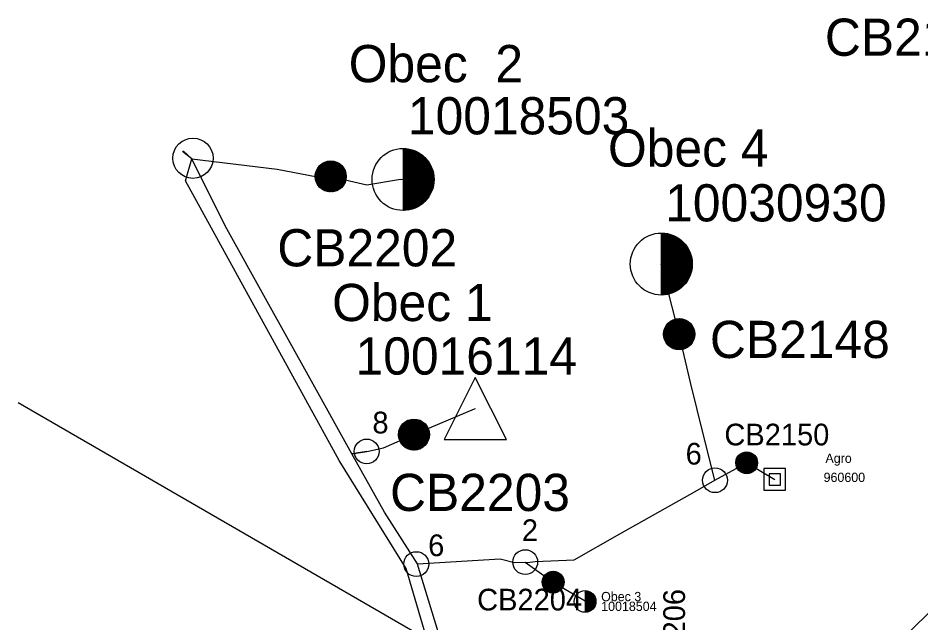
# Model space of a CAD drawing. Extents: x -763722 to -759486, y -1156407 to -1150938.
# Drawn here: x -763541 to -762085, y -1152498 to -1151523 of the extents above; entities that cross this region are included whole.
import ezdxf

# ---------------------------------------------------------------- set-up
doc = ezdxf.new("R2010")
doc.units = 0
for name, color, linetype in [('Default', 7, 'Continuous'), ('Vrstva 1', 7, 'Continuous'), ('Vrstva 18', 7, 'Continuous'), ('Vrstva 2', 7, 'Continuous'), ('Vrstva 3', 7, 'Continuous'), ('Vrstva 44', 7, 'Continuous'), ('Vrstva 5', 7, 'Continuous')]:
    doc.layers.add(name, color=color, linetype=linetype)

# ---------------------------------------------------------------- blocks, each defined once
blk = doc.blocks.new('PS140')
at = {"layer": 'Default'}
for p, q in [((-17.5, 0), (0, 17.5)), ((-17.4, -1.4), (1.4, 17.4)), ((-17.4, 1.5), (-1.5, 17.4)), ((-17.3, -2.6), (2.6, 17.3)), ((-17.2, 3.1), (-3.1, 17.2)), ((-17.1, -3.8), (3.8, 17.1)), ((-16.8, -4.9), (4.9, 16.8)), ((-16.8, 5), (-5, 16.8)), ((-16.4, -6), (6, 16.4)), ((-16, -7), (7, 16)), ((-15.9, 7.2), (-7.2, 15.9)), ((-15.6, -8), (8, 15.6)), ((-15.1, -8.9), (8.9, 15.1)), ((-14.5, -9.8), (9.8, 14.5)), ((-13.9, -10.6), (10.6, 13.9)), ((-13.8, 10.8), (-10.8, 13.8)), ((-13.3, -11.4), (11.4, 13.3)), ((-12.6, -12.1), (12.1, 12.6)), ((-11.9, -12.8), (12.8, 11.9)), ((-11.2, -13.5), (13.5, 11.2)), ((-10.4, -14.1), (14.1, 10.4)), ((-9.5, -14.7), (14.7, 9.5)), ((-8.6, -15.2), (15.2, 8.6)), ((-7.7, -15.7), (15.7, 7.7)), ((-6.7, -16.1), (16.1, 6.7)), ((-5.7, -16.5), (16.5, 5.7)), ((-4.6, -16.9), (16.9, 4.6)), ((-3.5, -17.1), (17.1, 3.5)), ((-2.3, -17.3), (17.3, 2.3)), ((-1, -17.5), (17.5, 1)), ((0.4, -17.5), (17.5, -0.4)), ((1.9, -17.4), (17.4, -1.9)), ((3.6, -17.1), (17.1, -3.6)), ((5.5, -16.6), (16.6, -5.5)), ((8, -15.6), (15.6, -8))]:
    blk.add_line(p, q, dxfattribs=at)
blk.add_circle((0, 0), 17.5, dxfattribs=at)
blk = doc.blocks.new('PS440')
at = {"layer": 'Default'}
for p, q in [((-25, 0.1), (-0.1, 25)), ((-24.9, -1.2), (1.2, 24.9)), ((-24.9, 1.6), (-1.6, 24.9)), ((-24.8, -2.6), (2.6, 24.8)), ((-24.8, 3.2), (-3.2, 24.8)), ((-24.7, -3.8), (3.8, 24.7)), ((-24.5, -5), (5, 24.5)), ((-24.5, 4.9), (-4.9, 24.5)), ((-24.2, -6.2), (6.2, 24.2)), ((-24.1, 6.7), (-6.7, 24.1)), ((-23.9, -7.3), (7.3, 23.9)), ((-23.6, -8.3), (8.3, 23.6)), ((-23.4, 8.8), (-8.8, 23.4)), ((-23.2, -9.4), (9.4, 23.2)), ((-22.7, -10.3), (10.3, 22.7)), ((-22.3, -11.3), (11.3, 22.3)), ((-22.3, 11.3), (-11.3, 22.3)), ((-21.8, -12.2), (12.2, 21.8)), ((-21.3, -13.1), (13.1, 21.3)), ((-20.7, -14), (14, 20.7)), ((-20.1, -14.8), (14.8, 20.1)), ((-19.9, 15.2), (-15.2, 19.9)), ((-19.5, -15.6), (15.6, 19.5)), ((-18.9, -16.4), (16.4, 18.9)), ((-18.2, -17.1), (17.1, 18.2)), ((-17.5, -17.8), (17.8, 17.5)), ((-16.8, -18.5), (18.5, 16.8)), ((-16, -19.2), (19.2, 16)), ((-15.2, -19.8), (19.8, 15.2)), ((-14.4, -20.4), (20.4, 14.4)), ((-13.6, -21), (21, 13.6)), ((-12.7, -21.5), (21.5, 12.7)), ((-11.8, -22), (22, 11.8)), ((-10.8, -22.5), (22.5, 10.8)), ((-9.9, -22.9), (22.9, 9.9)), ((-8.9, -23.4), (23.4, 8.9)), ((-7.8, -23.7), (23.7, 7.8)), ((-6.7, -24.1), (24.1, 6.7)), ((-5.6, -24.3), (24.3, 5.6)), ((-4.4, -24.6), (24.6, 4.4)), ((-3.2, -24.8), (24.8, 3.2)), ((-1.9, -24.9), (24.9, 1.9)), ((-0.6, -25), (25, 0.6)), ((0.8, -25), (25, -0.8)), ((2.3, -24.9), (24.9, -2.3)), ((4, -24.7), (24.7, -4)), ((5.7, -24.3), (24.3, -5.7)), ((7.7, -23.8), (23.8, -7.7)), ((10, -22.9), (22.9, -10)), ((12.9, -21.4), (21.4, -12.9))]:
    blk.add_line(p, q, dxfattribs=at)
blk.add_circle((0, 0), 25, dxfattribs=at)
blk = doc.blocks.new('PS820')
at = {"layer": 'Vrstva 2'}
blk.add_circle((0, 0), 32.5, dxfattribs=at)
blk = doc.blocks.new('PS610')
at = {"layer": 'Default'}
for p, q in [((0, 16.2), (1.3, 17.4)), ((0, 14.7), (2.5, 17.3)), ((0, 13.3), (3.7, 17.1)), ((0, 11.9), (4.9, 16.8)), ((0, 10.5), (5.9, 16.4)), ((0, 9.1), (7, 16)), ((0, 7.7), (7.9, 15.6)), ((0, 6.3), (8.8, 15.1)), ((0, 4.8), (9.7, 14.5)), ((0, 3.4), (10.5, 14)), ((0, 2), (11.3, 13.3)), ((0, 0.6), (12, 12.7)), ((0, -0.8), (12.8, 12)), ((0, -2.2), (13.4, 11.2)), ((0, -3.6), (14, 10.4)), ((0, -5), (14.6, 9.6)), ((0, -6.5), (15.2, 8.7)), ((0, -7.9), (15.6, 7.8)), ((0, -9.3), (16.1, 6.8)), ((0, -10.7), (16.5, 5.8)), ((0, -12.1), (16.8, 4.7)), ((0, -13.5), (17.1, 3.6)), ((0, -14.9), (17.3, 2.4)), ((0, -16.4), (17.4, 1.1)), ((0.3, -17.5), (17.5, -0.3)), ((1.8, -17.4), (17.4, -1.8)), ((3.5, -17.1), (17.1, -3.5)), ((5.4, -16.7), (16.7, -5.4)), ((7.8, -15.7), (15.6, -7.8))]:
    blk.add_line(p, q, dxfattribs=at)
blk.add_lwpolyline([(0, 17.5), (0, -17.5)], dxfattribs=at)
blk.add_circle((0, 0), 17.5, dxfattribs=at)
blk = doc.blocks.new('PS800')
at = {"layer": 'Vrstva 2'}
blk.add_circle((0, 0), 20, dxfattribs=at)
blk = doc.blocks.new('PS641')
at = {"layer": 'Vrstva 18'}
for points in [[(17.5, 17.5), (-17.5, 17.5)], [(-17.5, 17.5), (-17.5, -17.5)], [(17.5, -17.5), (17.5, 17.5)], [(9.2, 9.3), (-9.2, 9.3)], [(-9.2, 9.3), (-9.2, -9.2)], [(9.2, -9.2), (9.2, 9.3)], [(-9.2, -9.2), (9.2, -9.2)], [(-17.5, -17.5), (17.5, -17.5)]]:
    blk.add_lwpolyline(points, dxfattribs=at)
blk = doc.blocks.new('PS615')
at = {"layer": 'Default'}
for p, q in [((0, 49.1), (0.9, 50)), ((0, 46.3), (3.6, 49.9)), ((0, 47.7), (2.3, 49.9)), ((0, 44.8), (4.9, 49.8)), ((0, 43.4), (6.2, 49.6)), ((0, 42), (7.4, 49.4)), ((0, 40.6), (8.7, 49.2)), ((0, 39.2), (9.8, 49)), ((0, 37.8), (11, 48.8)), ((0, 36.4), (12.1, 48.5)), ((0, 34.9), (13.3, 48.2)), ((0, 33.5), (14.4, 47.9)), ((0, 32.1), (15.4, 47.6)), ((0, 30.7), (16.5, 47.2)), ((0, 29.3), (17.5, 46.8)), ((0, 27.9), (18.6, 46.4)), ((0, 26.5), (19.6, 46)), ((0, 25), (20.5, 45.6)), ((0, 23.6), (21.5, 45.1)), ((0, 22.2), (22.5, 44.7)), ((0, 20.8), (23.4, 44.2)), ((0, 19.4), (24.3, 43.7)), ((0, 18), (25.2, 43.2)), ((0, 16.6), (26.1, 42.6)), ((0, 15.1), (27, 42.1)), ((0, 13.7), (27.8, 41.5)), ((0, 12.3), (28.7, 41)), ((0, 10.9), (29.5, 40.4)), ((0, 9.5), (30.3, 39.8)), ((0, 8.1), (31.1, 39.2)), ((0, 6.7), (31.9, 38.5)), ((0, 5.2), (32.6, 37.9)), ((0, 3.8), (33.4, 37.2)), ((0, 2.4), (34.1, 36.5)), ((0, 1), (34.9, 35.9)), ((0, -0.4), (35.6, 35.1)), ((0, -1.8), (36.3, 34.4)), ((0, -3.2), (36.9, 33.7)), ((0, -4.7), (37.6, 32.9)), ((0, -6.1), (38.3, 32.2)), ((0, -7.5), (38.9, 31.4)), ((0, -8.9), (39.5, 30.6)), ((0, -10.3), (40.1, 29.8)), ((0, -11.7), (40.7, 29)), ((0, -13.1), (41.3, 28.2)), ((0, -14.6), (41.9, 27.3)), ((0, -16), (42.4, 26.5)), ((0, -17.4), (43, 25.6)), ((0, -18.8), (43.5, 24.7)), ((0, -20.2), (44, 23.8)), ((0, -21.6), (44.5, 22.8)), ((0, -23), (44.9, 21.9)), ((0, -24.5), (45.4, 20.9)), ((0, -25.9), (45.8, 20)), ((0, -27.3), (46.3, 19)), ((0, -28.7), (46.7, 18)), ((0, -30.1), (47, 16.9)), ((0, -31.5), (47.4, 15.9)), ((0, -32.9), (47.8, 14.8)), ((0, -34.4), (48.1, 13.7)), ((0, -35.8), (48.4, 12.6)), ((0, -37.2), (48.7, 11.5)), ((0, -38.6), (48.9, 10.3)), ((0, -40), (49.2, 9.1)), ((0, -41.4), (49.4, 7.9)), ((0, -42.8), (49.5, 6.7)), ((0, -44.3), (49.7, 5.4)), ((0, -45.7), (49.8, 4.2)), ((0, -47.1), (49.9, 2.8)), ((0, -48.5), (50, 1.5)), ((0, -49.9), (50, 0.1)), ((1.3, -50), (50, -1.3)), ((2.8, -49.9), (49.9, -2.8)), ((4.3, -49.8), (49.8, -4.3)), ((5.9, -49.6), (49.6, -5.9)), ((7.6, -49.4), (49.4, -7.6)), ((9.3, -49.1), (49.1, -9.3)), ((11.1, -48.8), (48.8, -11.1)), ((12.9, -48.3), (48.3, -12.9)), ((14.9, -47.7), (47.7, -14.9)), ((17.1, -47), (47, -17.1)), ((19.4, -46.1), (46.1, -19.4)), ((22, -44.9), (44.9, -22)), ((25, -43.3), (43.3, -25)), ((28.9, -40.8), (40.8, -28.9))]:
    blk.add_line(p, q, dxfattribs=at)
blk.add_lwpolyline([(0, 50), (0, -50)], dxfattribs=at)
blk.add_circle((0, 0), 50, dxfattribs=at)
blk = doc.blocks.new('PS685')
at = {"layer": 'Vrstva 44'}
for points in [[(-0.1, 50.1), (-50.1, -49.9)], [(49.9, -49.9), (-0.1, 50.1)], [(-50.1, -49.9), (49.9, -49.9)]]:
    blk.add_lwpolyline(points, dxfattribs=at)

msp = doc.modelspace()

# ---------------------------------------------------------------- linework, layer by layer
at = {"layer": 'Vrstva 1'}
for points in [[(-763260.3, -1151749.6), (-763275.6, -1151738)], [(-763274.3, -1151737.3), (-763273.7, -1151737.5), (-763260.3, -1151749.6)], [(-762679.1, -1152679.5), (-762707.2, -1152725.6), (-762830.5, -1152698.2), (-762914.8, -1152410.6), (-763023, -1152236.2), (-763270.4, -1151785.4), (-763260.3, -1151749.6)], [(-762978.5, -1152221.7), (-763002.6, -1152225.3), (-763070.3, -1152103.4), (-763139.1, -1151979.8), (-763206.8, -1151857.9), (-763260.3, -1151749.6)], [(-763260.3, -1151749.6), (-763122.7, -1151766.3), (-763047.3, -1151781), (-763036.5, -1151778.1)], [(-763036.5, -1151778.1), (-763036.5, -1151778.1), (-763036.4, -1151778.1), (-762978.2, -1151791.5), (-762924.1, -1151782.3), (-762919.9, -1151783)], [(-762474.8, -1152032.5), (-762474.8, -1152032.5), (-762502.7, -1151923.4), (-762503.6, -1151919.4)], [(-762417.1, -1152268.1), (-762435.1, -1152197.4), (-762456.4, -1152110.2), (-762474.8, -1152032.5)], [(-763540.5, -1152142.9), (-762777.6, -1152584.3)], [(-762902.3, -1152194.5), (-762902.3, -1152194.5), (-762902.3, -1152194.5), (-762804.7, -1152152.9), (-762803.3, -1152152.3)], [(-762978.5, -1152221.7), (-762951.6, -1152215.6), (-762902.3, -1152194.5), (-762902.3, -1152194.5)], [(-762896.4, -1152403.3), (-762896.5, -1152403.7), (-762896.6, -1152402.9), (-762949.9, -1152319.6), (-763002.6, -1152225.3), (-762978.5, -1152221.7)], [(-762417.1, -1152268.1), (-762389.1, -1152252.4), (-762366, -1152240)], [(-762366, -1152240), (-762320.8, -1152266.8)], [(-762207.1, -1152639.1), (-762207.4, -1152612.3), (-761833.8, -1152251.5)], [(-762449, -1152286), (-762417.1, -1152268.1)], [(-762723, -1152400.1), (-762722.9, -1152400.1), (-762722.9, -1152400.1), (-762721.3, -1152400.7), (-762720, -1152400.7), (-762715.3, -1152400.4), (-762706.7, -1152399.3), (-762644.1, -1152396.2), (-762570.6, -1152354.6), (-762449, -1152286)], [(-762896.6, -1152402.9), (-762763.4, -1152394.8), (-762740.4, -1152400.5), (-762723, -1152400.1)], [(-762679.1, -1152679.5), (-762723.4, -1152710.6), (-762812.4, -1152680), (-762896.5, -1152403.7), (-762896.4, -1152403.3)], [(-762723, -1152400.1), (-762723, -1152400.1), (-762677.9, -1152432.4)], [(-762677.9, -1152432.4), (-762677.9, -1152432.4), (-762626.6, -1152462.5), (-762626.5, -1152463.6)]]:
    msp.add_lwpolyline(points, dxfattribs=at)

# ---------------------------------------------------------------- block references
at = {"layer": 'Vrstva 2'}
for name, p, rotation in [('PS440', (-763036.5, -1151778.1), 30.00000000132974), ('PS440', (-762474.8, -1152032.5), -54.7698360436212), ('PS440', (-762902.3, -1152194.5), 23.00000008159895), ('PS140', (-762366, -1152240), 30.000000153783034), ('PS140', (-762677.9, -1152432.4), -81.6222832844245)]:
    msp.add_blockref(name, p, dxfattribs=dict(at, rotation=rotation))
at = {"layer": 'Vrstva 3'}
for name, p in [('PS615', (-762919.9, -1151783)), ('PS615', (-762503.6, -1151919.4)), ('PS685', (-762803.3, -1152152.3)), ('PS641', (-762320.8, -1152266.8)), ('PS610', (-762626.5, -1152463.6))]:
    msp.add_blockref(name, p, dxfattribs=at)
at = {"layer": 'Vrstva 5'}
for name, p, rotation in [('PS820', (-763258.6, -1151748.8), -60.000000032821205), ('PS800', (-762978.5, -1152221.7), -62.999999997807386), ('PS800', (-762417.1, -1152268.1), 30.00000000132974), ('PS800', (-762898.6, -1152403.3), -79.00000005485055), ('PS800', (-762723, -1152400.1), -3.8881916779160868)]:
    msp.add_blockref(name, p, dxfattribs=dict(at, rotation=rotation))

# ---------------------------------------------------------------- texts
at = {"layer": 'Vrstva 2'}
for s, height, p in [('CB2156', 60, (-762239.9, -1151583.6)), ('CB2202', 60, (-763122.6, -1151923.2)), ('CB2148', 60, (-762425.2, -1152071)), ('CB2150', 35, (-762401.9, -1152211.9)), ('CB2203', 60, (-762940.8, -1152317.7)), ('CB2204', 35, (-762800.5, -1152478.1))]:
    msp.add_text(s, height=height, dxfattribs=at).set_placement(p)
msp.add_text('CB2206', height=35, rotation=90, dxfattribs=at).set_placement((-762465.4, -1152612.6))
at = {"layer": 'Vrstva 3'}
for s, height, p in [('Obec  2', 60, (-763007.5, -1151626.2)), ('10018503', 60, (-762912.1, -1151710.3)), ('Obec 4', 60, (-762589.5, -1151762.3)), ('10030930', 60, (-762497.4, -1151850.7)), ('Obec 1', 60, (-763034.2, -1152011.4)), ('10016114', 60, (-762996.5, -1152097.7)), ('Agro', 15, (-762239, -1152240.1)), ('960600', 15, (-762242, -1152270.9)), ('Obec 3', 15, (-762600.6, -1152463.2)), ('10018504', 15, (-762600.5, -1152478.9))]:
    msp.add_text(s, height=height, dxfattribs=at).set_placement(p)
at = {"layer": 'Vrstva 5'}
for s, p in [('8', (-762969.3, -1152192.6)), ('6', (-762464.4, -1152242.8)), ('2', (-762728.4, -1152366.2)), ('6', (-762879.4, -1152390.5))]:
    msp.add_text(s, height=35, dxfattribs=at).set_placement(p)

doc.saveas('drawing.dxf')
